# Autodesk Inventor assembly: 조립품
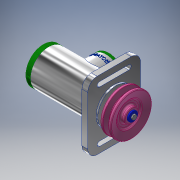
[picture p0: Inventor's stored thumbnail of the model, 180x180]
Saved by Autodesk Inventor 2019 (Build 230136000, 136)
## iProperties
Created: 2021-07
Part Number: 조립품
Material: 일반
Document SubType Name: Assembly
Designer: jun-2-6
Author: jun-2-6
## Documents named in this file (20)
- C:\Users\jun-2-6\Desktop\710706V1018\조립품.iam
- C:\Users\jun-2-6\Desktop\710706V1018\본체.ipt
- C:\Users\jun-2-6\Desktop\710706V1018\710706V1018\사이드 커버.ipt
- 사이드 커버.ipt
- C:\Users\jun-2-6\Desktop\710706V1018\710706V1018\축.ipt
- C:\Users\jun-2-6\Desktop\710706V1018\710706V1018\멈춤링 15 x 1.ipt
- C:\Users\jun-2-6\Desktop\710706V1018\710706V1018\멈춤링 35 x 1.6.ipt
- C:\Users\jun-2-6\Desktop\710706V1018\710706V1018\베어링 15 x 35 x 11.ipt
- C:\Users\jun-2-6\Desktop\710706V1018\710706V1018\부시1.ipt
- C:\Users\jun-2-6\Desktop\710706V1018\710706V1018\부시2.ipt
- C:\Users\jun-2-6\Desktop\710706V1018\710706V1018\와셔 10 x 21.ipt
- C:\Users\jun-2-6\Desktop\710706V1018\710706V1018\너트 M10.ipt
- C:\Users\jun-2-6\Desktop\710706V1018\710706V1018\오일 실 15 25 7.ipt
- C:\Users\jun-2-6\Desktop\710706V1018\710706V1018\키 4 x 4 x 18.ipt
- C:\Users\jun-2-6\Desktop\710706V1018\710706V1018\V-벨트풀리.ipt
- C:\Users\jun-2-6\Desktop\710706V1018\710706V1018\와셔 4 x 16.ipt
- C:\Users\jun-2-6\Desktop\710706V1018\710706V1018\볼트 M4 x 10.ipt
- C:\Users\jun-2-6\Desktop\710706V1018\710706V1018\탑 커버.ipt
- C:\Users\jun-2-6\Desktop\710706V1018\710706V1018\와셔 3 x 6.ipt
- C:\Users\jun-2-6\Desktop\710706V1018\710706V1018\십자볼트 M3 x 10.ipt
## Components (2 placed, 2 different names)
1. V-벨트풀리:1
2. ISO 4017 M4 x 10:1
